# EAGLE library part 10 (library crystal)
Monolithic Crystal Filters Source: www.golledge.com
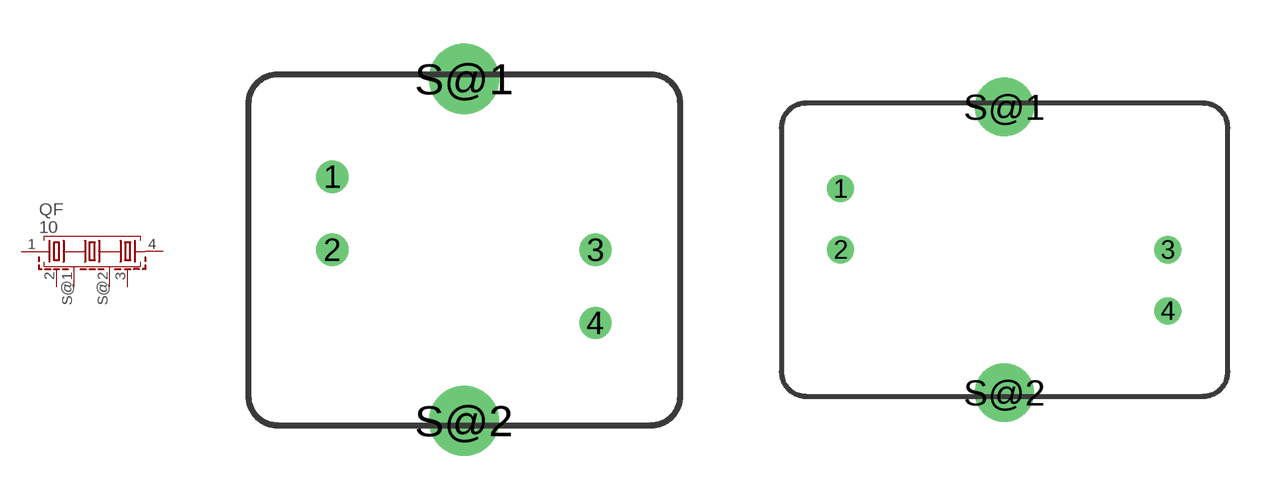
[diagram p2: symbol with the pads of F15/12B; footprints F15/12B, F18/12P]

Designator prefix QF

## 10G7C-12.5KHZ (OC_FARNELL: unknown; OC_NEWARK: unknown)  [F15/12B]
1  1  pas
2  2  pas
3  3  pas
4  4  pas
S@1  S  pas
S@2  S  pas

## 10G7D-12.5KHZ (OC_FARNELL: unknown; OC_NEWARK: unknown)  [F18/12P]
Pads as for F15/12B

## 10G12C-20.0KHZ (OC_FARNELL: unknown; OC_NEWARK: unknown)  [F15/12B]
Pads as for F15/12B

## 10G12D-20.0KHZ (OC_FARNELL: unknown; OC_NEWARK: unknown)  [F18/12P]
Pads as for F15/12B

## 10G15C-25.0KHZ (OC_FARNELL: unknown; OC_NEWARK: unknown)  [F15/12B]
Pads as for F15/12B

## 10G15D-25.0KHZ (OC_FARNELL: unknown; OC_NEWARK: unknown)  [F18/12P]
Pads as for F15/12B

## 10G20C-35.0KHZ (OC_FARNELL: unknown; OC_NEWARK: unknown)  [F15/12B]
Pads as for F15/12B

## 10G20D-35.0KHZ (OC_FARNELL: unknown; OC_NEWARK: unknown)  [F18/12P]
Pads as for F15/12B

## 10G30C-50.0KHZ (OC_FARNELL: unknown; OC_NEWARK: unknown)  [F15/12B]
Pads as for F15/12B

## 10G30D-50.0KHZ (OC_FARNELL: unknown; OC_NEWARK: unknown)  [F18/12P]
Pads as for F15/12B

## Footprint F15/12B (pad centres in mm)
Monolithic Crystal Filters Source: www.golledge.com
drill 0.6 pad 1.016 round: 1 -4.5,2.5; 2 -4.5,0; 3 4.5,0; 4 4.5,-2.5
drill 1.6 pad 1.93 round: S@1 0,5.85; S@2 0,-5.85

## Footprint F18/12P (pad centres in mm)
Monolithic Crystal Filters Source: www.golledge.com
drill 0.6 pad 1.016 round: 1 -6.7,2.5; 2 -6.7,0; 3 6.7,0; 4 6.7,-2.5
drill 1.6 pad 1.93 round: S@1 0,5.85; S@2 0,-5.85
